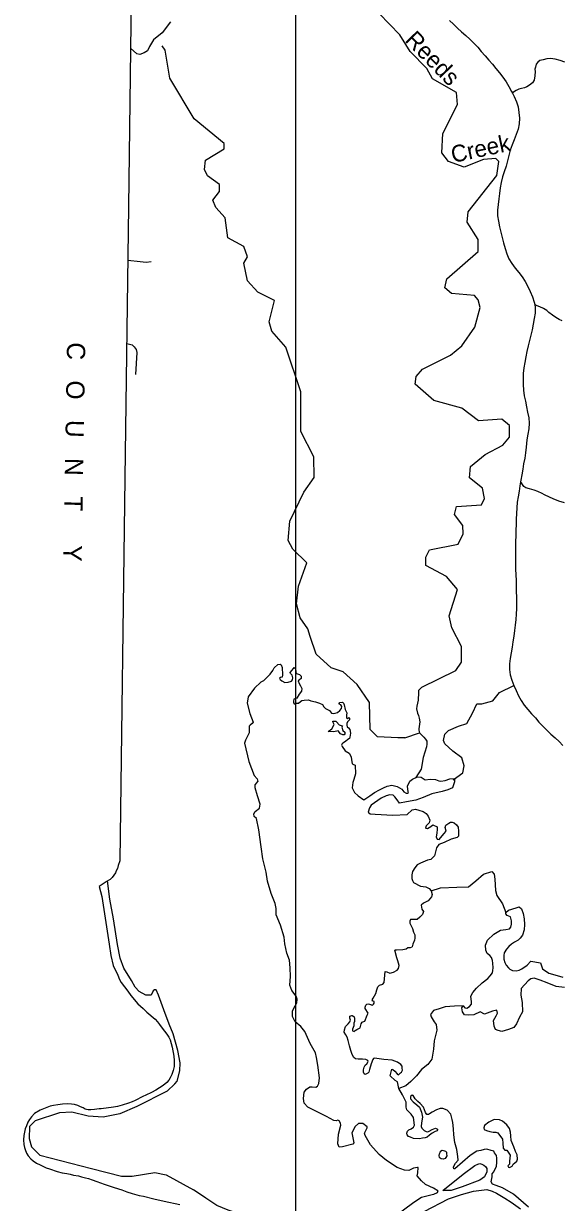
# Model space of a CAD drawing. Extents: x 2056842 to 2160602, y 826753 to 1016856.
# Drawn here: x 2056842 to 2061647, y 850316 to 860868 of the extents above; entities that cross this region are included whole.
import ezdxf

# ---------------------------------------------------------------- set-up
doc = ezdxf.new("R2010")
doc.units = 0
for name, color, linetype in [('Exist Boundary Political CountyLine', 7, 'Continuous'), ('Exist Boundary Political CountyLine Label', 7, 'Continuous'), ('Exist Hydrographic Creek Single Shore', 7, 'Continuous'), ('Exist Hydrographic Creek Single Shore Label', 7, 'Continuous'), ('Exist Hydrographic Island Shore', 7, 'Continuous'), ('Exist Hydrographic Lake Shore', 7, 'Continuous'), ('Exist Road Non-System Type 51', 7, 'Continuous'), ('Map Preparation Inset Cut Line', 7, 'Continuous')]:
    doc.layers.add(name, color=color, linetype=linetype)

msp = doc.modelspace()

# ---------------------------------------------------------------- linework, layer by layer
at = {"layer": 'Exist Boundary Political CountyLine'}
for points in [[(2058297, 904796), (2058304, 899211), (2058216, 894228), (2058154, 887047), (2058114, 884097), (2057934, 870695), (2057845, 864146), (2057782, 859231), (2057748, 856800), (2057704, 853375), (2057690, 853331), (2057682, 853305), (2057672, 853284), (2057665, 853266), (2057651, 853246), (2057635, 853225), (2057616, 853207), (2057583, 853188)], [(2057583, 853188), (2057580, 853186), (2057519, 853143), (2057542, 853053), (2057607, 852627), (2057623, 852526), (2057643, 852438), (2057687, 852351), (2057702, 852311), (2057715, 852283), (2057774, 852206), (2057803, 852169), (2057865, 852094), (2057913, 852051), (2057946, 852018), (2058019, 851957), (2058042, 851932), (2058060, 851908), (2058083, 851877), (2058104, 851849), (2058124, 851822), (2058141, 851794), (2058153, 851770), (2058164, 851738), (2058171, 851705), (2058186, 851625), (2058189, 851585), (2058190, 851559), (2058190, 851533), (2058181, 851497), (2058168, 851461), (2058154, 851432), (2058141, 851410), (2058123, 851388), (2058092, 851363), (2058060, 851340), (2058027, 851320), (2057987, 851299), (2057937, 851276), (2057910, 851263), (2057842, 851228), (2057815, 851217), (2057781, 851205)], [(2057781, 851205), (2057725, 851185), (2057684, 851173), (2057648, 851168), (2057536, 851154), (2057520, 851153), (2057476, 851148), (2057444, 851144), (2057420, 851145), (2057404, 851147), (2057392, 851151), (2057374, 851162), (2057352, 851172), (2057327, 851183), (2057297, 851191), (2057271, 851196), (2057231, 851199), (2057191, 851196), (2057149, 851190), (2057111, 851183), (2057081, 851176), (2056990, 851141), (2056939, 851111), (2056912, 851083), (2056894, 851058), (2056881, 851034), (2056867, 851000), (2056856, 850974), (2056850, 850945), (2056845, 850915), (2056842, 850875), (2056845, 850833), (2056851, 850806), (2056856, 850788), (2056868, 850758), (2056883, 850732), (2056907, 850707), (2056928, 850689), (2056958, 850668), (2056990, 850652), (2057045, 850626), (2057073, 850616), (2057142, 850592), (2057188, 850582), (2057230, 850575), (2057260, 850568), (2057288, 850561), (2057334, 850553), (2057361, 850546), (2057397, 850537), (2057423, 850529), (2057455, 850518), (2057499, 850503), (2057562, 850480), (2057654, 850450), (2057721, 850427), (2057767, 850412), (2057814, 850397), (2057878, 850379), (2057916, 850371), (2058009, 850349), (2058101, 850327), (2058242, 850296)], [(2060428, 850234), (2060644, 850347), (2060761, 850388), (2060868, 850417), (2060987, 850430), (2061037, 850417), (2061075, 850398), (2061149, 850355), (2061207, 850318), (2061289, 850258)]]:
    msp.add_lwpolyline(points, dxfattribs=at)
at = {"layer": 'Exist Hydrographic Creek Single Shore'}
for points in [[(2060761, 855156), (2060761, 855293), (2060676, 855459), (2060651, 855567), (2060726, 855802), (2060626, 855919), (2060442, 856018), (2060442, 856093), (2060476, 856158), (2060733, 856209), (2060776, 856300), (2060774, 856375), (2060700, 856475), (2060716, 856544), (2060942, 856559), (2060967, 856618), (2060950, 856710), (2060833, 856801), (2060841, 856902), (2060974, 857011), (2061131, 857093), (2061191, 857167), (2061191, 857269), (2061123, 857326), (2060915, 857311), (2060765, 857426), (2060514, 857493), (2060348, 857641), (2060356, 857710), (2060414, 857774), (2060664, 857900), (2060764, 857983), (2060880, 858152), (2060929, 858328), (2060912, 858394), (2060879, 858434), (2060672, 858451), (2060612, 858502), (2060630, 858583), (2060912, 858827), (2060911, 858935), (2060812, 859092), (2060820, 859183), (2061078, 859509), (2061095, 859634), (2061069, 859660), (2060960, 859653), (2060786, 859584), (2060644, 859633), (2060586, 859710), (2060594, 859884), (2060726, 860143), (2060717, 860252), (2060502, 860374), (2060450, 860467), (2060301, 860618), (2060209, 860768), (2060025, 860958)], [(2060654, 860897), (2060690, 860862), (2060725, 860827), (2060762, 860794), (2060800, 860761), (2060837, 860728), (2060873, 860693), (2060907, 860656), (2060939, 860617), (2060972, 860580), (2061005, 860542), (2061038, 860505), (2061070, 860466), (2061101, 860427), (2061132, 860388), (2061160, 860346), (2061186, 860304), (2061210, 860260), (2061219, 860244)], [(2059408, 855381), (2059385, 855449), (2059319, 855549), (2059285, 855674), (2059302, 855831), (2059376, 856040), (2059251, 856164), (2059209, 856240), (2059224, 856414), (2059350, 856674), (2059442, 856806), (2059441, 856990), (2059324, 857216), (2059323, 857573), (2059189, 857973), (2059064, 858114), (2059039, 858199), (2059089, 858389), (2058938, 858464), (2058847, 858564), (2058813, 858723), (2058846, 858781), (2058813, 858873), (2058671, 858949), (2058646, 859130), (2058562, 859223), (2058537, 859289), (2058595, 859364), (2058595, 859429), (2058487, 859504), (2058461, 859563), (2058469, 859645), (2058636, 859747), (2058636, 859796), (2058369, 860015), (2058151, 860380), (2058110, 860630), (2058084, 860670)], [(2061686, 860523), (2061646, 860539), (2061600, 860549), (2061558, 860555), (2061526, 860553), (2061492, 860545), (2061464, 860537), (2061446, 860523), (2061430, 860505), (2061423, 860479), (2061419, 860460), (2061420, 860439), (2061419, 860401), (2061411, 860361), (2061397, 860339), (2061371, 860318), (2061345, 860302), (2061326, 860294), (2061299, 860288), (2061276, 860282), (2061251, 860270), (2061237, 860260), (2061225, 860252), (2061219, 860244)], [(2061219, 860244), (2061234, 860215), (2061255, 860169), (2061268, 860122), (2061276, 860072), (2061280, 860021), (2061278, 859972), (2061269, 859923), (2061252, 859876), (2061234, 859829), (2061215, 859782), (2061197, 859736), (2061184, 859687), (2061173, 859639), (2061160, 859591), (2061145, 859542), (2061130, 859495), (2061118, 859446), (2061109, 859397), (2061102, 859348), (2061095, 859298), (2061089, 859248), (2061085, 859198), (2061085, 859148), (2061092, 859099), (2061102, 859050), (2061113, 859001), (2061126, 858952), (2061139, 858905), (2061153, 858856), (2061167, 858807), (2061185, 858762), (2061212, 858720), (2061242, 858680), (2061274, 858641), (2061304, 858601), (2061331, 858559), (2061356, 858515), (2061377, 858470), (2061396, 858423), (2061413, 858375), (2061417, 858353)], [(2061417, 858353), (2061422, 858327), (2061420, 858277), (2061413, 858228), (2061403, 858178), (2061393, 858128), (2061381, 858080), (2061369, 858031), (2061357, 857983), (2061347, 857934), (2061338, 857885), (2061329, 857835), (2061321, 857786), (2061315, 857736), (2061313, 857687), (2061314, 857636), (2061318, 857586), (2061324, 857537), (2061334, 857488), (2061344, 857439), (2061353, 857390), (2061363, 857340), (2061368, 857291), (2061364, 857241), (2061355, 857192), (2061346, 857143), (2061339, 857077), (2061333, 857027), (2061327, 856978), (2061318, 856928), (2061310, 856879), (2061301, 856830), (2061293, 856780), (2061291, 856766)], [(2061664, 858207), (2061637, 858219), (2061605, 858237), (2061575, 858257), (2061544, 858281), (2061524, 858301), (2061496, 858319), (2061464, 858333), (2061440, 858341), (2061417, 858353)], [(2061291, 856766), (2061285, 856731), (2061277, 856682), (2061268, 856632), (2061261, 856583), (2061257, 856533), (2061253, 856483), (2061252, 856433), (2061250, 856383), (2061248, 856333), (2061247, 856283), (2061246, 856233), (2061245, 856183), (2061244, 856133), (2061244, 856083), (2061245, 856033), (2061246, 855983), (2061248, 855933), (2061250, 855883), (2061251, 855833), (2061252, 855783), (2061253, 855733), (2061253, 855683), (2061253, 855633), (2061250, 855583), (2061247, 855533), (2061242, 855483), (2061237, 855434), (2061229, 855384), (2061221, 855335), (2061214, 855286), (2061206, 855236), (2061198, 855186), (2061191, 855136), (2061190, 855086), (2061197, 855038), (2061212, 854990), (2061231, 854943), (2061251, 854897), (2061273, 854852), (2061297, 854808), (2061324, 854766), (2061356, 854727), (2061389, 854690), (2061423, 854653), (2061455, 854615), (2061489, 854578), (2061524, 854542), (2061560, 854508), (2061599, 854475), (2061637, 854442), (2061670, 854406)], [(2061683, 856577), (2061633, 856593), (2061581, 856613), (2061548, 856629), (2061505, 856651), (2061484, 856663), (2061445, 856679), (2061412, 856693), (2061369, 856703), (2061338, 856713), (2061321, 856723), (2061307, 856743), (2061299, 856757), (2061291, 856766)], [(2060253, 854474), (2060191, 854474), (2060011, 854485), (2059945, 854548), (2059937, 854791), (2059828, 854951), (2059702, 855065), (2059595, 855100), (2059461, 855224), (2059408, 855381)], [(2060376, 854898), (2060406, 854929), (2060711, 855077), (2060761, 855152), (2060761, 855156)], [(2060376, 854898), (2060376, 854880), (2060373, 854813), (2060363, 854758), (2060360, 854733), (2060369, 854696), (2060376, 854675), (2060382, 854650), (2060388, 854619), (2060379, 854555), (2060379, 854542), (2060385, 854518), (2060425, 854481), (2060440, 854462), (2060452, 854444), (2060452, 854419), (2060449, 854395), (2060419, 854299), (2060400, 854195), (2060352, 854118)], [(2060688, 854098), (2060775, 854161), (2060787, 854224), (2060764, 854297), (2060685, 854354), (2060611, 854422), (2060600, 854450), (2060611, 854507), (2060645, 854541), (2060736, 854580), (2060809, 854603), (2060860, 854694), (2060900, 854778), (2060945, 854778), (2061041, 854807), (2061103, 854880), (2061231, 854943)], [(2060253, 854474), (2060385, 854518)], [(2060489, 853104), (2060574, 853131), (2060721, 853137), (2060823, 853142), (2060891, 853193), (2060959, 853255), (2061033, 853278), (2061055, 853255), (2061061, 853210), (2061067, 853108), (2061078, 853063), (2061129, 852989), (2061159, 852912)], [(2060776, 852076), (2060699, 852072), (2060614, 852067), (2060563, 852050), (2060512, 852033), (2060484, 851999), (2060489, 851976), (2060518, 851931), (2060535, 851908), (2060540, 851857), (2060518, 851761), (2060512, 851687), (2060495, 851597), (2060461, 851551), (2060405, 851506), (2060359, 851449), (2060308, 851398), (2060263, 851359), (2060202, 851335)]]:
    msp.add_lwpolyline(points, dxfattribs=at)
at = {"layer": 'Exist Hydrographic Island Shore'}
for points in [[(2059623, 854595), (2059611, 854618), (2059611, 854624), (2059614, 854625), (2059636, 854624), (2059643, 854618), (2059667, 854591), (2059693, 854582), (2059698, 854582), (2059692, 854570), (2059700, 854541), (2059717, 854525), (2059717, 854510), (2059711, 854502), (2059699, 854502), (2059678, 854509), (2059657, 854536), (2059620, 854527), (2059579, 854532), (2059568, 854530), (2059568, 854530), (2059600, 854555), (2059623, 854595)], [(2060588, 850784), (2060608, 850778), (2060619, 850776), (2060626, 850767), (2060628, 850752), (2060629, 850732), (2060622, 850719), (2060615, 850709), (2060602, 850703), (2060580, 850706), (2060570, 850711), (2060564, 850719), (2060563, 850736), (2060565, 850750), (2060570, 850763), (2060575, 850774)], [(2060575, 850774), (2060588, 850784)], [(2060594, 850423), (2060777, 850569), (2060882, 850646), (2060909, 850659), (2060925, 850663), (2060944, 850658), (2060962, 850649), (2060977, 850637), (2060989, 850620), (2060988, 850590), (2060967, 850546), (2060927, 850514), (2060769, 850455), (2060669, 850421), (2060625, 850421), (2060594, 850423)]]:
    msp.add_lwpolyline(points, dxfattribs=at)
at = {"layer": 'Exist Hydrographic Lake Shore'}
for points in [[(2058989, 854985), (2059048, 855043), (2059073, 855076), (2059084, 855100), (2059118, 855131), (2059140, 855134), (2059149, 855129), (2059156, 855104), (2059161, 855040), (2059158, 855018), (2059142, 855016), (2059134, 855008), (2059138, 854996), (2059154, 854984), (2059181, 854971), (2059210, 854974), (2059241, 854981), (2059250, 854995), (2059253, 855011), (2059247, 855036), (2059230, 855050), (2059229, 855059), (2059247, 855080), (2059263, 855104), (2059277, 855094), (2059278, 855063), (2059285, 855050), (2059313, 855042), (2059326, 855028), (2059326, 855006), (2059311, 854995), (2059301, 854985), (2059309, 854961), (2059321, 854940), (2059333, 854917), (2059330, 854893), (2059308, 854865), (2059288, 854831), (2059261, 854821), (2059257, 854804), (2059257, 854794), (2059261, 854784), (2059275, 854773), (2059284, 854784), (2059302, 854786), (2059321, 854800), (2059333, 854810), (2059352, 854811), (2059393, 854814), (2059412, 854807), (2059455, 854798), (2059490, 854786), (2059519, 854773), (2059530, 854753), (2059543, 854737), (2059581, 854719), (2059599, 854694), (2059615, 854692), (2059631, 854696)], [(2058989, 854985), (2058966, 854973), (2058908, 854918), (2058851, 854843), (2058844, 854785), (2058867, 854691), (2058898, 854614), (2058889, 854603), (2058870, 854589), (2058861, 854578), (2058862, 854519), (2058828, 854455), (2058820, 854427), (2058857, 854263), (2058907, 854137), (2058933, 854109), (2058938, 854083)], [(2059631, 854696), (2059652, 854702), (2059674, 854719), (2059687, 854737), (2059691, 854756), (2059681, 854771), (2059670, 854774), (2059666, 854783), (2059673, 854790), (2059697, 854793), (2059707, 854786), (2059711, 854771), (2059719, 854729), (2059735, 854699), (2059732, 854678), (2059731, 854655), (2059742, 854647), (2059753, 854657), (2059760, 854651), (2059760, 854635)], [(2059760, 854635), (2059741, 854617), (2059734, 854602), (2059734, 854587), (2059739, 854573), (2059749, 854563), (2059763, 854549), (2059768, 854515), (2059766, 854498)], [(2059766, 854498), (2059761, 854481), (2059758, 854470), (2059743, 854460), (2059724, 854443), (2059708, 854433), (2059693, 854420), (2059688, 854408), (2059694, 854396), (2059719, 854359), (2059755, 854338), (2059775, 854303), (2059776, 854279), (2059782, 854246), (2059789, 854238), (2059809, 854231)], [(2059809, 854231), (2059814, 854153), (2059798, 854102), (2059788, 854075), (2059782, 854027)], [(2059454, 851656), (2059408, 851737), (2059359, 851845), (2059325, 851892), (2059272, 851933), (2059249, 851979), (2059249, 852029), (2059261, 852056), (2059287, 852103), (2059291, 852134), (2059283, 852162), (2059243, 852212), (2059225, 852260), (2059231, 852337), (2059228, 852417), (2059222, 852483), (2059197, 852546), (2059179, 852632), (2059173, 852689), (2059142, 852798), (2059104, 852890), (2059103, 852948), (2059094, 852991), (2059058, 853081), (2059025, 853191), (2059013, 853271), (2058984, 853391), (2058968, 853500), (2058947, 853650), (2058926, 853752), (2058906, 853771), (2058903, 853794), (2058916, 853816), (2058954, 853844), (2058960, 853880), (2058936, 853954), (2058915, 854028), (2058915, 854055), (2058929, 854071), (2058938, 854083)], [(2059782, 854027), (2059804, 853985), (2059836, 853954), (2059887, 853920)], [(2059887, 853920), (2059942, 853954), (2059983, 853984), (2060027, 854010), (2060064, 854028), (2060096, 854042), (2060137, 854050), (2060185, 854039), (2060228, 854014), (2060247, 853992), (2060266, 853979), (2060279, 853980), (2060286, 853984), (2060284, 853992), (2060278, 854042), (2060298, 854086), (2060323, 854106), (2060367, 854125), (2060402, 854121), (2060436, 854099), (2060482, 854105), (2060529, 854103), (2060559, 854091), (2060576, 854086), (2060614, 854094), (2060657, 854109), (2060700, 854111), (2060700, 854081), (2060681, 854028), (2060640, 854008), (2060590, 853993), (2060495, 853972), (2060418, 853939), (2060353, 853917), (2060270, 853903), (2060208, 853891)], [(2060208, 853891), (2060187, 853921), (2060164, 853947), (2060149, 853961), (2060120, 853965), (2060088, 853956), (2060042, 853934), (2059954, 853873)], [(2059954, 853873), (2059939, 853849), (2059925, 853810), (2059944, 853793), (2059990, 853790), (2060147, 853782), (2060276, 853789), (2060276, 853789)], [(2060276, 853789), (2060319, 853829), (2060350, 853836), (2060381, 853827), (2060418, 853816), (2060444, 853796), (2060464, 853772), (2060478, 853738), (2060471, 853713), (2060446, 853686), (2060440, 853666), (2060456, 853663), (2060487, 853680), (2060505, 853696), (2060545, 853677), (2060545, 853657), (2060541, 853621), (2060535, 853587), (2060545, 853567), (2060562, 853564), (2060604, 853614), (2060623, 853639), (2060614, 853673), (2060621, 853693), (2060647, 853711), (2060662, 853720), (2060679, 853721), (2060695, 853714), (2060717, 853696), (2060732, 853674), (2060734, 853639), (2060734, 853595), (2060723, 853582), (2060668, 853568), (2060607, 853539), (2060559, 853520), (2060559, 853520)], [(2060559, 853520), (2060537, 853489), (2060519, 853417), (2060488, 853386), (2060458, 853380), (2060394, 853353), (2060364, 853338), (2060343, 853312), (2060323, 853278), (2060317, 853247), (2060316, 853216), (2060324, 853196), (2060333, 853180), (2060394, 853146), (2060442, 853142), (2060473, 853125), (2060489, 853104), (2060499, 853071), (2060492, 853052), (2060464, 853015), (2060422, 852996), (2060401, 852977), (2060408, 852941), (2060423, 852920), (2060412, 852892), (2060388, 852868), (2060365, 852849), (2060306, 852848), (2060300, 852834), (2060299, 852815), (2060324, 852769), (2060333, 852736), (2060343, 852711), (2060345, 852681), (2060340, 852664), (2060326, 852627), (2060320, 852604)], [(2058049, 852170), (2058028, 852219), (2058013, 852219), (2058003, 852209), (2057985, 852170), (2057936, 852170), (2057878, 852204), (2057842, 852242), (2057808, 852301), (2057739, 852414), (2057706, 852501), (2057683, 852626), (2057647, 852854), (2057614, 853031), (2057592, 853193)], [(2060851, 852110), (2060845, 852161), (2060864, 852195), (2060895, 852233), (2060947, 852280), (2060998, 852319), (2061019, 852343), (2061038, 852372), (2061043, 852393), (2061045, 852417), (2061043, 852456), (2061039, 852482), (2061031, 852509), (2061014, 852527), (2060990, 852544), (2060980, 852575), (2060976, 852618), (2060994, 852662), (2061051, 852716), (2061110, 852754), (2061159, 852759), (2061191, 852764), (2061203, 852781), (2061210, 852808), (2061208, 852837), (2061199, 852873), (2061171, 852883), (2061157, 852898), (2061159, 852912), (2061182, 852932), (2061250, 852953), (2061278, 852963), (2061298, 852945), (2061314, 852901), (2061322, 852853), (2061325, 852805), (2061322, 852755), (2061308, 852708), (2061288, 852682), (2061270, 852663), (2061237, 852646), (2061208, 852629), (2061186, 852608), (2061164, 852582), (2061144, 852550), (2061142, 852526), (2061140, 852493), (2061150, 852464), (2061161, 852441), (2061181, 852415), (2061195, 852404), (2061219, 852393), (2061250, 852390), (2061278, 852396), (2061302, 852407), (2061350, 852440), (2061382, 852476), (2061468, 852461), (2061488, 852407), (2061543, 852369), (2061618, 852348), (2061670, 852332)], [(2059981, 852115), (2059963, 852120), (2059965, 852127), (2059966, 852134), (2059972, 852144), (2059996, 852187), (2060004, 852219), (2060013, 852245), (2060027, 852260), (2060057, 852269), (2060070, 852283), (2060078, 852382), (2060092, 852381), (2060119, 852369), (2060152, 852376), (2060186, 852395), (2060198, 852410), (2060203, 852437), (2060193, 852477), (2060184, 852505), (2060166, 852573), (2060171, 852577), (2060180, 852577), (2060238, 852579), (2060266, 852587), (2060280, 852597), (2060304, 852599), (2060320, 852604)], [(2061685, 852239), (2061609, 852250), (2061527, 852282), (2061466, 852306), (2061413, 852322), (2061381, 852316), (2061357, 852298), (2061295, 852231), (2061294, 852172), (2061305, 852104), (2061307, 852021), (2061282, 851974), (2061254, 851913), (2061230, 851883), (2061181, 851865), (2061124, 851845), (2061090, 851854), (2061067, 851865), (2061055, 851893), (2061048, 851943), (2061073, 851985), (2061084, 852011), (2061079, 852036), (2061038, 852028), (2060968, 852001), (2060929, 852022), (2060871, 851996), (2060824, 851991), (2060789, 851996), (2060772, 852023), (2060765, 852059), (2060776, 852076), (2060790, 852059), (2060809, 852055), (2060833, 852070), (2060852, 852090), (2060851, 852110)], [(2058197, 851377), (2058218, 851400), (2058241, 851494), (2058243, 851564), (2058223, 851676), (2058182, 851825), (2058144, 851912), (2058098, 852040), (2058049, 852170)], [(2060202, 851335), (2060188, 851394), (2060169, 851408), (2060124, 851449), (2060137, 851509), (2060148, 851505), (2060164, 851492), (2060186, 851466), (2060198, 851459), (2060205, 851464), (2060217, 851475), (2060226, 851483), (2060233, 851500), (2060232, 851519), (2060230, 851536), (2060220, 851551), (2060188, 851571), (2060142, 851588), (2060067, 851594), (2060004, 851605), (2059983, 851608), (2059973, 851604), (2059967, 851594), (2059954, 851557), (2059939, 851506), (2059932, 851483), (2059923, 851473), (2059898, 851462), (2059891, 851466), (2059884, 851481), (2059885, 851503), (2059891, 851526), (2059899, 851543), (2059915, 851556), (2059927, 851577), (2059922, 851585), (2059905, 851594), (2059876, 851597), (2059838, 851597), (2059813, 851602), (2059799, 851612), (2059782, 851640), (2059770, 851676), (2059758, 851717), (2059748, 851766), (2059739, 851795), (2059725, 851817), (2059710, 851839), (2059714, 851861), (2059722, 851891), (2059746, 851915), (2059763, 851933), (2059768, 851948), (2059762, 851966), (2059763, 851983), (2059779, 851990), (2059782, 851990), (2059790, 851986), (2059800, 851977), (2059804, 851965), (2059804, 851936), (2059797, 851919), (2059797, 851895), (2059785, 851866), (2059787, 851853), (2059800, 851847), (2059811, 851854), (2059824, 851864), (2059854, 851880), (2059858, 851892), (2059864, 851915), (2059872, 851928), (2059878, 851931), (2059895, 851938), (2059902, 851952), (2059912, 851976), (2059917, 851991), (2059925, 852010), (2059898, 852051), (2059899, 852065), (2059905, 852081), (2059915, 852089), (2059925, 852092), (2059937, 852091), (2059957, 852083), (2059963, 852079), (2059974, 852091), (2059981, 852100), (2059981, 852115)], [(2060549, 850419), (2060510, 850442), (2060439, 850476), (2060403, 850509), (2060366, 850553), (2060370, 850581), (2060374, 850627), (2060368, 850629), (2060333, 850623), (2060290, 850601), (2060252, 850605), (2060185, 850628), (2060091, 850690), (2060026, 850745), (2059948, 850832), (2059898, 850914), (2059893, 850937), (2059904, 850959), (2059918, 850982), (2059916, 850992), (2059878, 851022), (2059841, 851023), (2059809, 850995), (2059781, 850940), (2059797, 850848), (2059790, 850838), (2059698, 850813), (2059667, 850809), (2059655, 850840), (2059661, 850928), (2059683, 851008), (2059678, 851026), (2059666, 851045), (2059655, 851051), (2059639, 851047), (2059619, 851050), (2059552, 851086), (2059387, 851168), (2059353, 851204), (2059348, 851247), (2059352, 851303), (2059373, 851330), (2059405, 851351), (2059426, 851350), (2059458, 851348), (2059473, 851355), (2059485, 851379), (2059491, 851430), (2059476, 851545), (2059464, 851612), (2059454, 851656)], [(2058197, 851377), (2058128, 851313), (2057857, 851174), (2057704, 851110), (2057555, 851080), (2057420, 851087), (2057274, 851123), (2057164, 851118), (2056946, 851046), (2056895, 850994), (2056893, 850889), (2056913, 850812), (2056987, 850738), (2057450, 850620), (2057719, 850550), (2057814, 850552), (2058018, 850583), (2058119, 850564), (2058362, 850428)], [(2060290, 850967), (2060311, 850974), (2060331, 850989), (2060342, 851008), (2060333, 851076), (2060312, 851107), (2060273, 851145), (2060267, 851168), (2060265, 851213), (2060234, 851280), (2060202, 851335)], [(2060452, 851103), (2060439, 851120), (2060421, 851168), (2060393, 851200), (2060372, 851220), (2060346, 851244), (2060329, 851274), (2060319, 851277), (2060304, 851265), (2060306, 851243), (2060328, 851217), (2060363, 851189), (2060386, 851169), (2060404, 851124), (2060413, 851080), (2060404, 851029), (2060401, 850996), (2060408, 850979), (2060428, 850961), (2060445, 850950), (2060461, 850948), (2060473, 850953), (2060500, 850968), (2060514, 850975), (2060529, 850979), (2060541, 850975), (2060548, 850971)], [(2060693, 850921), (2060690, 850975), (2060683, 851030), (2060677, 851059), (2060667, 851105), (2060632, 851142), (2060596, 851156), (2060572, 851156), (2060538, 851144), (2060500, 851124), (2060476, 851110), (2060466, 851104), (2060452, 851103)], [(2060548, 850971), (2060548, 850964), (2060543, 850958), (2060526, 850950), (2060499, 850937), (2060475, 850919), (2060455, 850900), (2060437, 850893), (2060414, 850890), (2060386, 850886), (2060333, 850889), (2060306, 850899), (2060287, 850907), (2060275, 850920), (2060273, 850937), (2060277, 850954), (2060290, 850967)], [(2061189, 850628), (2061198, 850630), (2061215, 850640), (2061224, 850658), (2061240, 850671), (2061257, 850686), (2061262, 850703), (2061260, 850741), (2061244, 850773), (2061229, 850814), (2061207, 850869), (2061203, 850911), (2061199, 850946), (2061191, 850977), (2061168, 851010), (2061130, 851043), (2061101, 851056), (2061054, 851059), (2061005, 851034), (2060968, 851003), (2060962, 850984), (2060964, 850968), (2060984, 850960), (2061016, 850952), (2061045, 850944), (2061068, 850944), (2061086, 850940), (2061128, 850881), (2061132, 850845), (2061134, 850802), (2061148, 850784), (2061167, 850784), (2061180, 850767), (2061198, 850739), (2061190, 850684), (2061192, 850659), (2061177, 850642), (2061183, 850632), (2061189, 850628)], [(2061361, 850272), (2061226, 850389), (2061128, 850447), (2061072, 850468), (2061039, 850478), (2061026, 850499), (2061035, 850545), (2061035, 850573), (2061051, 850590), (2061075, 850640), (2061079, 850674), (2061079, 850712), (2061075, 850736), (2061058, 850761), (2061051, 850774), (2061028, 850780), (2060987, 850791), (2060966, 850790), (2060935, 850780), (2060899, 850774), (2060838, 850735), (2060703, 850616), (2060694, 850616), (2060691, 850630), (2060696, 850647), (2060707, 850667), (2060732, 850694), (2060729, 850728), (2060721, 850790), (2060703, 850851), (2060693, 850921)], [(2058951, 850180), (2058815, 850200), (2058674, 850246), (2058572, 850287), (2058472, 850354), (2058362, 850428)], [(2060549, 850419), (2060544, 850401), (2060510, 850386), (2060403, 850360), (2060334, 850314), (2060244, 850246), (2060150, 850175)]]:
    msp.add_lwpolyline(points, dxfattribs=at)
at = {"layer": 'Exist Road Non-System Type 51'}
for points in [[(2058156, 860884), (2058083, 860784), (2058004, 860723), (2057970, 860663), (2057952, 860623), (2057922, 860606), (2057883, 860593), (2057857, 860597), (2057800, 860649)], [(2057775, 858749), (2057886, 858738), (2057938, 858733), (2057984, 858740)], [(2057765, 858004), (2057813, 857993), (2057833, 857975), (2057850, 857951), (2057855, 857923), (2057844, 857728)]]:
    msp.add_lwpolyline(points, dxfattribs=at)
at = {"layer": 'Map Preparation Inset Cut Line'}
msp.add_lwpolyline([(2059277, 845852), (2104036, 845852), (2104036, 868311), (2085975, 868309), (2085982, 877260), (2059277, 877260), (2059277, 845852)], dxfattribs=at)

# ---------------------------------------------------------------- texts
at = {"layer": 'Exist Boundary Political CountyLine Label'}
msp.add_text('C   O   U   N   T     Y', height=164.04, rotation=269.0323, dxfattribs=at).set_placement((2057231, 858016))
at = {"layer": 'Exist Hydrographic Creek Single Shore Label'}
for s, rotation, p in [('Reeds', 314.522, (2060247, 860713)), ('Creek', 12.0534, (2060685, 859620))]:
    msp.add_text(s, height=150, rotation=rotation, dxfattribs=at).set_placement(p)

doc.saveas('drawing.dxf')
